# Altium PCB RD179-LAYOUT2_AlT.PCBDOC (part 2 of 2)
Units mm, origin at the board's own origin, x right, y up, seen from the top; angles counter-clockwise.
Board outline 130 x 85 mm, 2 copper layers (TOP, BOTTOM), stack 0 mm thick; 157 components, 104 nets, 823 pads, 0 vias.
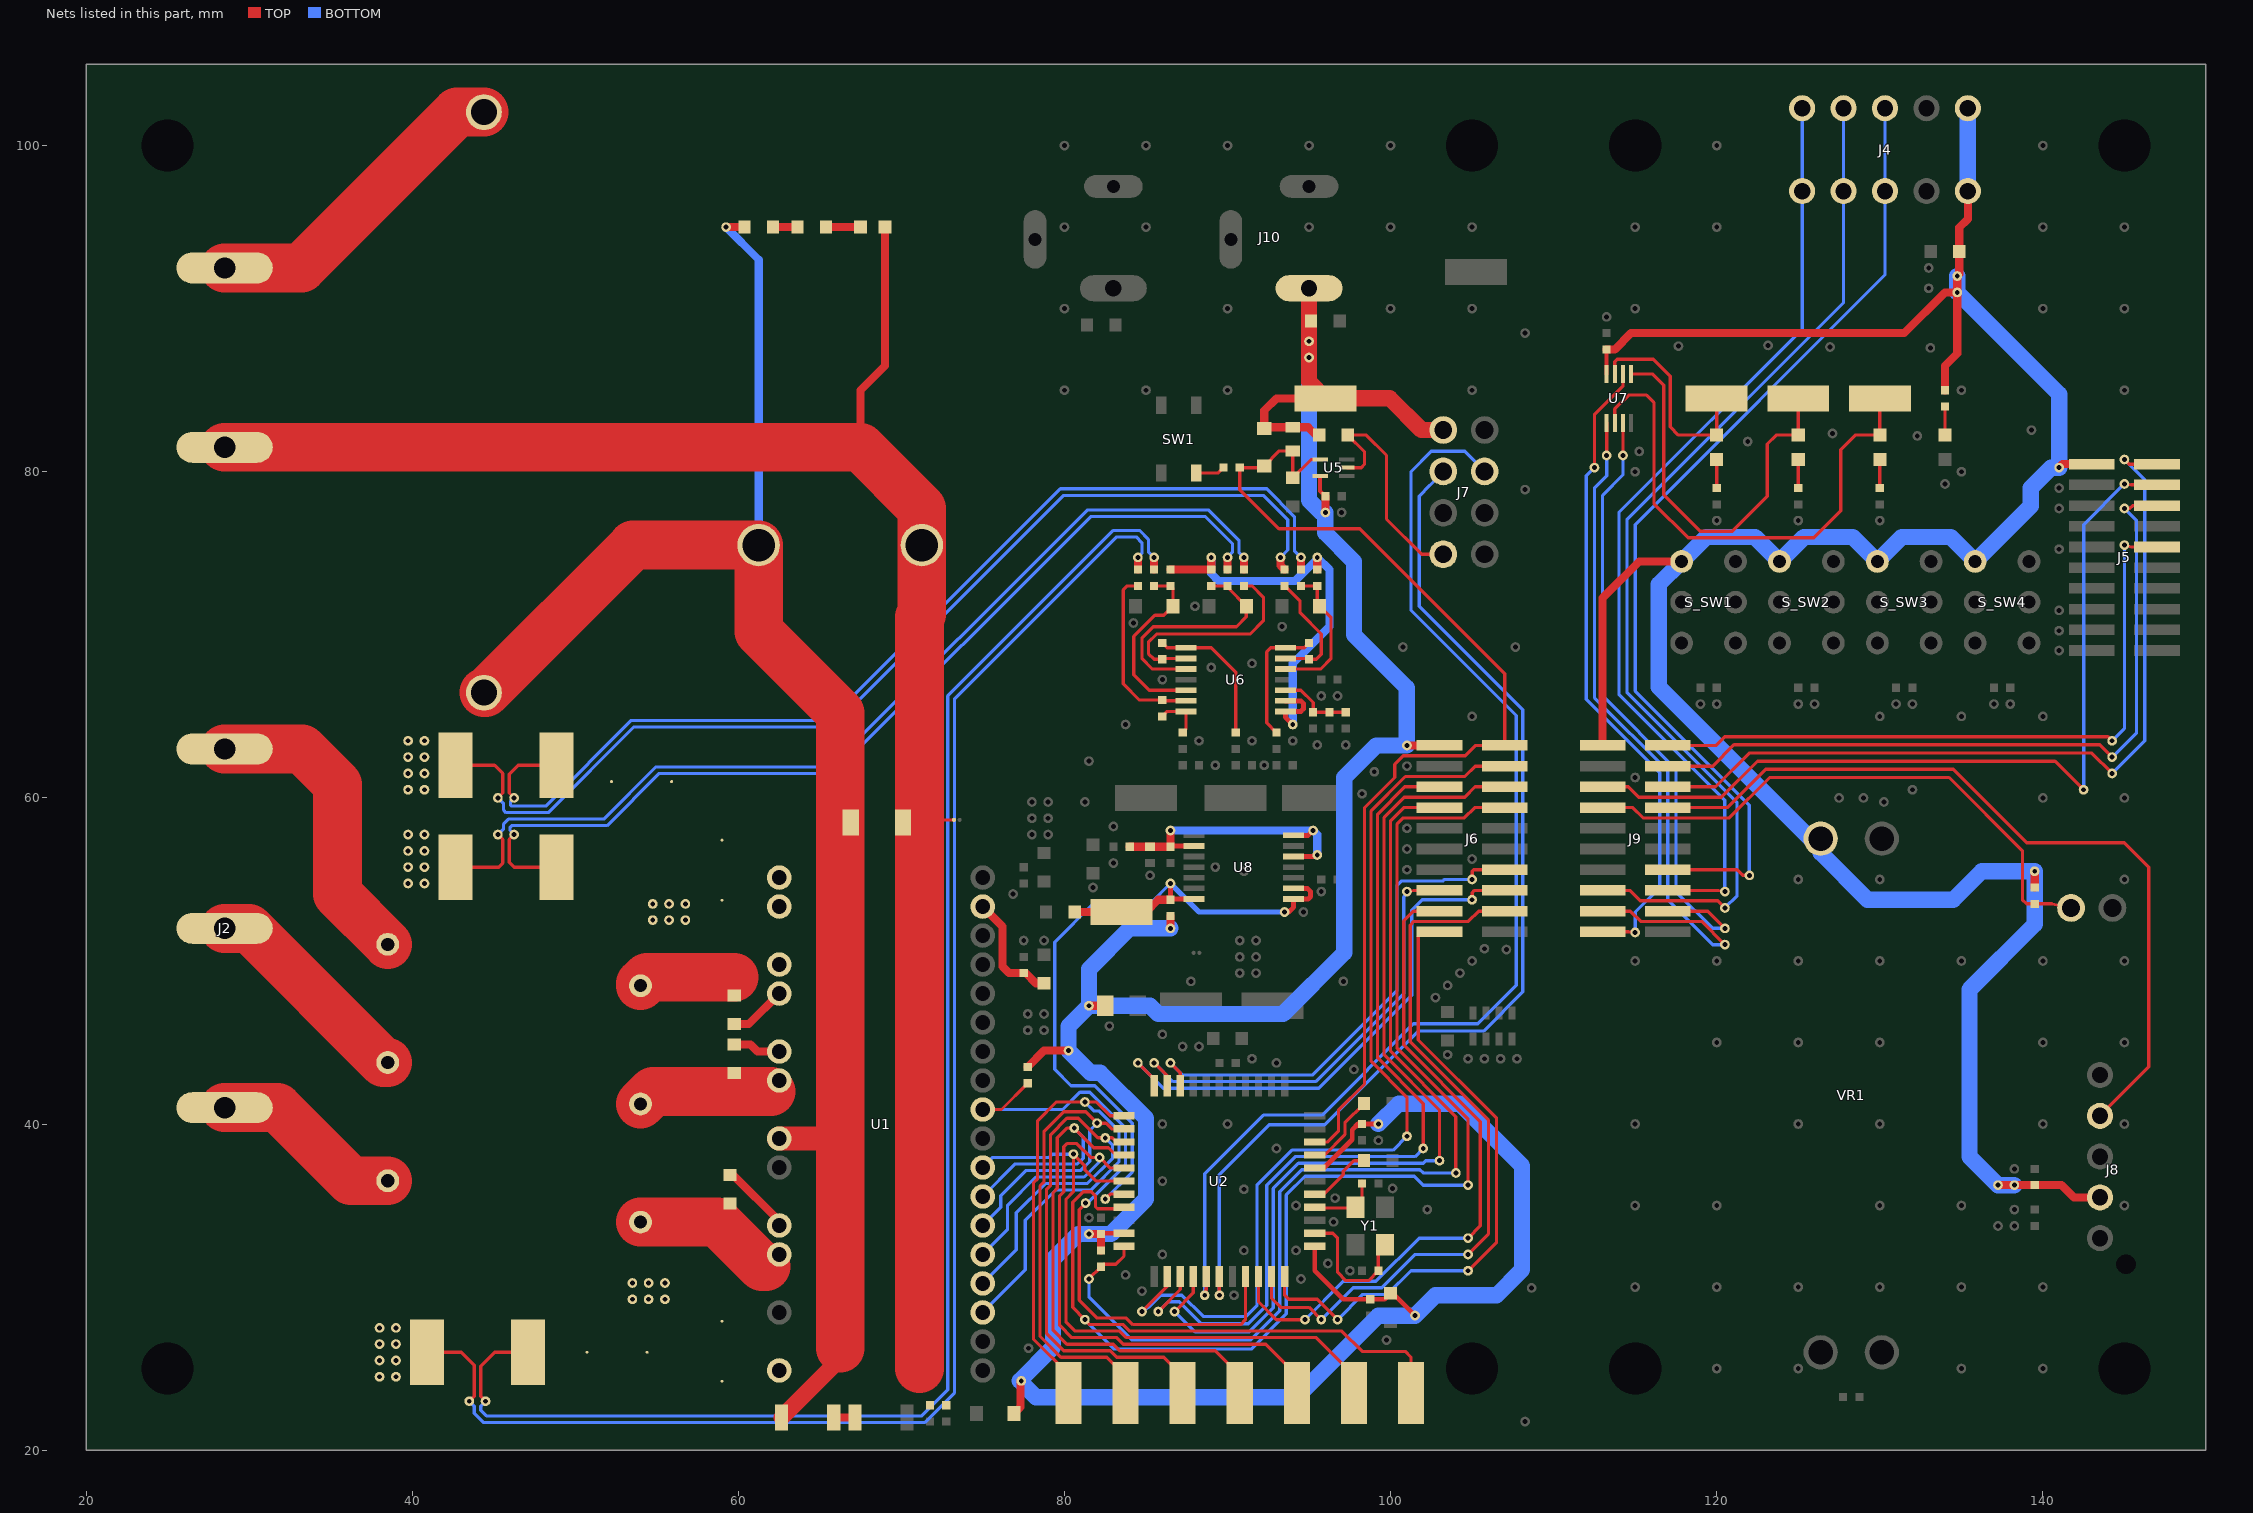
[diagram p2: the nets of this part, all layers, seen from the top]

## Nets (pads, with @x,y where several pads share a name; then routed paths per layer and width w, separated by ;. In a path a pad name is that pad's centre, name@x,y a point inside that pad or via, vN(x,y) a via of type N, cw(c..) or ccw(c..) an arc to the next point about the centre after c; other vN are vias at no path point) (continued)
LED1: J6.17 pad.@94.75,28 pad.@104.75,33 U2.20 | length 41.1
  TOP w0.2: U2.20@91.9,30.65 91.9,29.1 93,28 pad.@94.75,28 ; J6.17@103,53.055 101.4,53.055 100.8,52.455 100.8,44.85 105.5,40.15 105.5,33.75 pad.@104.75,33
  BOTTOM w0.2: pad.@94.75,28 97.1,30.35 99.1,30.35 101.75,33 pad.@104.75,33
LED1X: J9.17 pad.@113.25,81 pad.@120.5,51 U7.1 | length 44.4
  TOP w0.2: J9.17@113,53.055 114.695,53.055 115.33,52.42 119.08,52.42 pad.@120.5,51 ; pad.@113.25,81 U7.1@113.25,83
  BOTTOM w0.2: pad.@113.25,81 113.25,79.75 112.5,79 112.5,66.15 117,61.65 117,53.75 119.75,51 pad.@120.5,51
LED2: J6.18 pad.@95.75,28 pad.@104.75,32 U2.21 | length 44.5
  TOP w0.2: U2.21@92.7,30.65 92.7,29.3 93.25,28.75 95,28.75 pad.@95.75,28 ; pad.@104.75,32 106,33.25 106,40.25 101.2,45.05 101.2,52.2 101.42,52.42 104.77,52.42 105.405,53.055 J6.18@107,53.055
  BOTTOM w0.2: pad.@95.75,28 97.7,29.95 99.45,29.95 101.5,32 pad.@104.75,32
LED2X: J9.18 pad.@114.25,81 pad.@120.5,52 U7.3 | length 39
  TOP w0.2: pad.@114.25,81 U7.3@114.25,83 ; J9.18@117,53.055 119.445,53.055 pad.@120.5,52
  BOTTOM w0.2: pad.@114.25,81 114.25,79.8 113,78.55 113,66.25 117.5,61.75 117.5,54.25 119.75,52 pad.@120.5,52
LED3: J6.19 pad.@96.75,28 pad.@104.75,31 U2.22 | length 38.9
  TOP w0.2: U2.22@93.5,30.65 93.5,29.5 93.75,29.25 95.5,29.25 pad.@96.75,28 ; J6.19@103,51.785 101.985,51.785 101.7,51.5 101.7,45.15 106.5,40.35 106.5,32.75 pad.@104.75,31
  BOTTOM w0.2: pad.@96.75,28 98.3,29.55 99.8,29.55 101.25,31 pad.@104.75,31
LED3X: J9.19 pad.@112.5,80.25 pad.@115,51.75 U7.6 | length 39.7
  TOP w0.2: pad.@112.5,80.25 112.5,83.5 114.25,85.25 U7.6@114.25,86 ; J9.19@113,51.785 114.581,51.785 pad.@115,51.75
  BOTTOM w0.2: pad.@112.5,80.25 112,79.75 112,66.05 116.5,61.55 116.5,54.5 115,53 pad.@115,51.75
N16845104: pad.@89,74.75 pad.@94,64.5 pad.@95.5,74.75 R34.2 R42.2 R49.2 U6.1 U6.2 | length 27.5
  TOP w0.3: U6.2@93.55,65.95 94.5,65.95 94.65,65.8 94.65,65.45 94.5,65.3 U6.1@93.55,65.3 93.55,64.95 pad.@94,64.5
  TOP w0.5: R49.2@86.5,74 R42.2@89,74 pad.@89,74.75 ; R34.2@95.5,74 pad.@95.5,74.75
  BOTTOM w0.5: pad.@89,74.75 89,73.75 89.45,73.3 94.15,73.3 95.5,74.65 pad.@95.5,74.75 96.25,74 96.25,70.5 94,68.25 pad.@94,64.5
N16845135: D6.3 R47.1 R49.1 U6.12 | length 11.4
  TOP w0.2: R47.1@85.5,73 R49.1@86.5,73 86.65,72.85 D6.3@86.65,71.75 86.1,71.2 85.55,71.2 84.25,69.9 84.25,67.55 85.2,66.6 U6.12@87.45,66.6
N16845212: C12.1 U1.22 | length 3.5
  TOP w0.5: C12.1@59.75,46.125 60.639,46.125 U1.22@62.515,48.001
N16845252: SJP1.1 SJP3.2 U1.30
N16845280: pad.@44.5,23 pad.@85.5,74.75 R10.2 R47.2 SJP3.1 | length 96.9
  TOP w0.2: pad.@44.5,23 44.2,23.3 44.2,25.15 45.05,26 R10.2@47.1,26
  TOP w0.5: R47.2@85.5,74 pad.@85.5,74.75
  BOTTOM w0.2: pad.@44.5,23 44.2,22.7 44.2,22.45 44.55,22.1 71.25,22.1 72.85,23.7 72.85,66.25 83,76.4 84.6,76.4 85.15,75.85 85.15,75.1 pad.@85.5,74.75
N16845354: J2.1 L4.1 | length 18.9
  TOP w3: J2.1@28.5,63 33.25,63 35.42,60.83 35.42,54.1 L4.1@38.5,51.02
N16845382: C20.1 U2.27 | length 4
  TOP w0.2: U2.27@95.35,35.7 95.9,35.7 97.1,36.9 97.1,37.1 97.75,37.75 C20.1@98.375,37.75
N16845404: pad.@46.25,57.75 pad.@53.5,29.25 pad.@53.5,30.25 pad.@54.5,29.25 pad.@54.5,30.25 pad.@54.75,52.5 pad.@54.75,53.5 pad.@55.5,29.25 pad.@55.5,30.25 pad.@55.75,52.5 pad.@55.75,53.5 pad.@56.75,52.5 pad.@56.75,53.5 pad.@90,74.75 R11.2 R41.2 SJP1.2 SJP2.1 U1.20 | length 60
  TOP w0.2: pad.@46.25,57.75 45.95,57.45 45.95,56.05 46.25,55.75 R11.2@48.85,55.75
  TOP w0.5: R41.2@90,74 pad.@90,74.75
  BOTTOM w0.2: pad.@46.25,57.75 46,58 46,58.2 46.1,58.3 51.95,58.3 55.15,61.5 65.85,61.5 81.6,77.25 88.65,77.25 90.3,75.6 90.3,75.05 pad.@90,74.75
N16845509: LED1.1 TST1.1 U7.7 | length 13.1
  TOP w0.2: U7.7@113.75,86 113.75,86.75 113.9,86.9 116.1,86.9 117.15,85.85 117.15,82.75 117.65,82.25 LED1.1@120,82.25 TST1.1@120,84.5
N16845541: R37.1 R39.2 U6.8 | length 8.9
  TOP w0.2: R37.1@86,69.5 86.3,69.2 U6.8@87.45,69.2 89,69.2 90.5,67.7 R39.2@90.5,64
N16845574: R27.1 R29.2 U6.7 | length 8
  TOP w0.2: R29.2@93,64 92.4,64.6 92.4,68.95 92.65,69.2 U6.7@93.55,69.2 94.7,69.2 R27.1@95,69.5
N16845576: R37.2 R38.1 U6.9 | length 13.7
  TOP w0.2: U6.9@87.45,68.55 86.05,68.55 R37.2@86,68.5 85.5,68.5 85.15,68.85 85.15,69.55 85.65,70.05 91.4,70.05 92.2,70.85 92.2,72.3 91.5,73 R38.1@91,73
N16845623: SJP2.2 SJP4.2 U1.19
N16845627: C10.2 L3.2 U1.24 | length 8.3
  TOP w3: L3.2@54,41.23 54.77,42 62,42
N16845698: C35.1 pad.@86.5,58 pad.@95.5,56.5 pad.@95.25,58 R33.2 R48.1 U8.5 U8.7 U8.9 | length 18.1
  TOP w0.3: C35.1@86.5,57 86.55,57.05 U8.9@87.95,57.05 ; U8.5@94.05,56.4 95.4,56.4 pad.@95.5,56.5 ; U8.7@94.05,57.7 94.95,57.7 pad.@95.25,58
  TOP w0.5: R33.2@84,57 R48.1@85.25,57 C35.1@86.5,57 pad.@86.5,58
  BOTTOM w0.5: pad.@86.5,58 pad.@95.25,58 95.5,57.75 pad.@95.5,56.5
N16845732: D4.3 R32.1 R34.1 U6.5 | length 8.9
  TOP w0.2: U6.5@93.55,67.9 95.7,67.9 96.35,68.55 96.35,71.05 D4.3@95.65,71.75 95.5,71.9 R34.1@95.5,73 R32.1@94.5,73
N16845798: C12.2 L4.2 U1.21 | length 6
  TOP w3: L4.2@54,48.48 54,48.609 54.391,49 59.75,49
N16846050: C21.1 U2.30 | length 4.8
  TOP w0.2: U2.30@95.35,38.1 95.95,38.1 97.2,39.35 97.2,40.075 C21.1@98.375,41.25
N16846127: F1.1 J1.1 | length 19.9
  TOP w3: J1.1@28.5,92.5 33.2,92.5 42.75,102.05 F1.1@44.4,102.05
N16846135: C10.1 U1.23 | length 2.9
  TOP w0.5: C10.1@59.75,44.875 60.75,44.875 61.18,44.445 U1.23@62.515,44.445
N16846208: R27.2 R28.1 U6.6 | length 7.5
  TOP w0.2: R28.1@93.5,73 94.45,72.05 94.45,71.35 95.75,70.05 95.75,68.8 95.45,68.5 R27.2@95,68.5 94.9,68.5 94.85,68.55 U6.6@93.55,68.55
N16846250: C14.1 C15.1 U1.17 | length 7.2
  TOP w0.5: U1.17@74.985,53.335 76.2,52.12 76.2,49.65 76.6,49.25 C15.1@77.5,49.25 77.625,49.25 78.25,48.625 C14.1@78.75,48.625
N16846295: D5.3 R41.1 R42.1 U6.10 | length 14.5
  TOP w0.2: U6.10@87.45,67.9 85.4,67.9 84.75,68.55 84.75,69.8 85.45,70.5 90.55,70.5 91.15,71.1 D5.3@91.15,71.75 90,72.9 R41.1@90,73 R42.1@89,73
N16846330: C9.1 U1.27 | length 4.4
  TOP w0.5: C9.1@59.5,36.875 59.675,36.875 62.515,34.035 U1.27@62.515,33.777
N16846464: R44.1 R46.2 U6.14 | length 3
  TOP w0.2: R44.1@86,65 86.3,65.3 U6.14@87.45,65.3 87.45,64.2 R46.2@87.25,64
N16846585: C24.1 U2.26 Y1.3 | length 4.3
  TOP w0.2: U2.26@95.35,34.9 95.4,34.85 97.8,34.85 Y1.3@97.85,34.9 98.25,35.3 C24.1@98.25,36.5
N16846619: C16.1 U2.24 Y1.1 | length 8.4
  TOP w0.2: U2.24@95.35,33.3 96.45,33.3 96.75,33 96.75,30.9 97.25,30.4 98.65,30.4 C16.1@99.25,31 99.25,32.25 99.6,32.6 Y1.1@99.65,32.6
N16846795: C9.2 L2.2 U1.28 | length 8.8
  TOP w3: L2.2@54,33.98 58.72,33.98 61.45,31.25 61.7,31.25
N16847047: J2.3 L2.1 | length 11.9
  TOP w3: J2.3@28.5,41 31.75,41 36.23,36.52 L2.1@38.5,36.52
N16847149: LED3.1 TST3.1 U7.2 | length 31.8
  TOP w0.2: U7.2@113.75,83 113.75,83.85 114.6,84.7 115.7,84.7 116.15,84.25 116.15,78.05 118.25,75.95 125.95,75.95 127.6,77.6 127.6,81.35 128.5,82.25 LED3.1@130,82.25 TST3.1@130,84.5
N16847210: R44.2 R45.1 U6.13 | length 11
  TOP w0.2: R45.1@84.5,73 83.85,73 83.6,72.75 83.6,67 84.6,66 R44.2@86,66 86.05,65.95 U6.13@87.45,65.95
N16847386: LED2.1 TST2.1 U7.5 | length 24.7
  TOP w0.2: U7.5@114.75,86 116.05,86 116.75,85.3 116.75,78.6 119,76.35 120.95,76.35 123.1,78.5 123.1,81.7 123.65,82.25 LED2.1@125,82.25 TST2.1@125,84.5
N16847824: pad.@46.25,60 pad.@94.5,74.75 R12.2 R32.2 SJP4.1 | length 65.5
  TOP w0.2: pad.@46.25,60 45.95,60.3 45.95,61.45 46.5,62 R12.2@48.85,62
  TOP w0.5: R32.2@94.5,74 pad.@94.5,74.75
  BOTTOM w0.2: pad.@46.25,60 46.025,59.775 46.025,59.575 46.1,59.5 48.184,59.5 53.434,64.75 65.55,64.75 79.75,78.95 92.4,78.95 94.1,77.25 94.1,75.15 pad.@94.5,74.75
N16854424: J2.2 L3.1 | length 13.4
  TOP w3: J2.2@28.5,52 30,52 38.23,43.77 L3.1@38.5,43.77
N16936899: LEDP1.1 R3.2 | length 2.1
  TOP w0.5: R3.2@65.375,95 LEDP1.1@67.5,95
N16997175: C13.2 R6.2 R7.1 U6.3 | length 4.6
  TOP w0.2: U6.3@93.55,66.6 94.5,66.6 95.25,65.85 C13.2@95.25,65.25 R7.1@96.25,65.25 R6.2@97.25,65.25
N168453641: R1.2 R3.1 | length 1.5
  TOP w0.5: R1.2@62.125,95 R3.1@63.625,95
N168456521: LED1.2 R25.1 | length 1.8
  TOP w0.2: R25.1@120,79 LED1.2@120,80.75
N168457540: LED3.2 R36.1 | length 1.8
  TOP w0.2: R36.1@130,79 LED3.2@130,80.75
N168464781: R16.2 SW1.2 | length 1.8
  TOP w0.2: SW1.2@88.075,79.925 89.425,79.925 R16.2@89.75,80.25
N168466560: R2.2 R4.1 | length 1.3
  TOP w0.5: R2.2@65.85,22 R4.1@67.15,22
N168470940: LEDP2.1 R15.1 | length 1.7
  TOP w0.2: LEDP2.1@134,82.25 R15.1@134,84
N168482340: LED2.2 R30.1 | length 1.8
  TOP w0.2: R30.1@125,79 LED2.2@125,80.75
NBOOT: J6.7 pad.@81.5,30.5 pad.@104,37 R17.2 U2.11 | length 63.3
  TOP w0.2: pad.@81.5,30.5 R17.2@82.25,31.25 82.4,31.4 83.15,31.4 83.65,31.9 U2.11@83.65,32.5 ; J6.7@103,59.405 100.805,59.405 100,58.6 100,44.45 104,40.45 pad.@104,37
  BOTTOM w0.2: pad.@81.5,30.5 81.5,29.4 84.15,26.75 91.397,26.75 93.2,28.553 93.2,35.85 94.55,37.2 101.8,37.2 102,37 pad.@104,37
NBOOTX: J9.7 JP1.1 R22.2 | length 35
  TOP w0.2: J9.7@113,59.405 114.845,59.405 115.48,58.77 120.77,58.77 123.25,61.25 134.25,61.25 138.75,56.75 138.75,53.75 139,53.5 R22.2@139.5,53.5 140.567,53.5 JP1.1@141.73,53.25
NEMG: pad.@82.5,35.4 pad.@86.5,54.75 pad.@93.5,53 R35.2 R43.2 TP11.1 U2.7 U8.1 U8.2 U8.14 | length 49.2
  TOP w0.2: pad.@82.5,35.4 82.8,35.7 U2.7@83.65,35.7
  TOP w0.3: pad.@86.5,54.75 R35.2@86.5,53.75 86.55,53.8 U8.14@87.95,53.8 ; pad.@93.5,53 93.75,53 94.05,53.3 U8.1@94.05,53.8 94.95,53.8 95.1,53.95 95.1,54.25 94.9,54.45 U8.2@94.05,54.45
  TOP w0.5: R43.2@80.625,53 TP11.1@83.5,53 85,53 85.75,53.75 R35.2@86.5,53.75
  BOTTOM w0.2: pad.@82.5,35.4 84.15,37.05 84.15,40.05 81.85,42.35 80.4,42.35 79.4,43.35 79.4,51.15 81.75,53.5 85.25,53.5 pad.@86.5,54.75
  BOTTOM w0.3: pad.@86.5,54.75 88.25,53 pad.@93.5,53
NRESET: C27.1 D2.1 J6.2 R14.1 R16.1 U2.31 U5.4 | length 67
  TOP w0.2: U2.31@95.35,38.9 96.15,38.9 96.8,39.55 96.8,40.85 98.4,42.45 98.4,59.4 100.25,61.25 100.25,62.05 100.78,62.58 104.58,62.58 105.215,63.215 J6.2@107,63.215 107,67.609 98.109,76.5 93.15,76.5 90.75,78.9 R16.1@90.75,80.25 92.15,80.25 D2.1@92.25,80.35 93.175,81.275 R14.1@94,81.275 C27.1@94,79.625 95.125,80.75 U5.4@95.675,80.75
NRESETX: J5.10 J9.2 pad.@144.25,63.5 pad.@145,75.5 | length 41.9
  TOP w0.2: J9.2@117,63.215 119.965,63.215 120.5,63.75 144,63.75 pad.@144.25,63.5 ; pad.@145,75.5 145.404,75.385 J5.10@147,75.385
  BOTTOM w0.2: pad.@144.25,63.5 145,64.25 pad.@145,75.5
NRESIN: J7.7 R54.2 U5.2 | length 14.5
  TOP w0.2: U5.2@97.325,80.25 98.2,80.25 98.4,80.45 98.4,81.225 R54.2@97.375,82.25 98.5,82.25 99.75,81 99.75,77.1 101.91,74.94 J7.7@103.23,74.94
NSD: pad.@81.3,35.15 R13.1 U1.10 U2.19 | length 38.9
  TOP w0.2: U1.10@74.985,40.889 76.139,40.889 R13.1@77.75,42.5 ; pad.@81.3,35.15 80.9,34.75 80.9,29.2 82,28.1 83.8,28.1 84.2,27.7 90.8,27.7 91.1,28 U2.19@91.1,30.65
  BOTTOM w0.2: U1.10@74.985,40.889 79.889,40.889 80.95,41.95 81.55,41.95 83.75,39.75 83.75,37.5 81.4,35.15 pad.@81.3,35.15
NSYNC_SPI: J6.14 pad.@86.5,43.75 pad.@105,55 U2.42 | length 31.7
  TOP w0.2: pad.@86.5,43.75 87.1,43.15 U2.42@87.1,42.35 ; pad.@105,55 105,55.5 105.095,55.595 J6.14@107,55.595
  BOTTOM w0.2: pad.@86.5,43.75 87.25,43 95.2,43 100.4,48.2 100.4,54.65 100.65,54.9 103.2,54.9 103.3,55 pad.@105,55
NSYNC_SPIX: J4.3 J4.3-2 J9.14 pad.@122,55.25 | length 61.4
  TOP w0.2: J9.14@117,55.595 121.25,55.595 121.595,55.25 pad.@122,55.25
  BOTTOM w0.2: pad.@122,55.25 122,59.55 115,66.55 115,76.75 130.32,92.07 J4.3-2@130.32,97.21 J4.3@130.32,102.29
PGND: C8.2 C36.2 C37.2 J1.2 LEDP1.2 pad.@38,24.5 pad.@38,25.5 pad.@38,26.5 pad.@38,27.5 pad.@39,24.5 pad.@39,25.5 pad.@39,26.5 pad.@39,27.5 pad.@39.75,54.75 pad.@39.75,55.75 pad.@39.75,56.75 pad.@39.75,57.75 pad.@39.75,60.5 pad.@39.75,61.5 pad.@39.75,62.5 pad.@39.75,63.5 pad.@40.75,54.75 pad.@40.75,55.75 pad.@40.75,56.75 pad.@40.75,57.75 pad.@40.75,60.5 pad.@40.75,61.5 pad.@40.75,62.5 pad.@40.75,63.5 pad.@43.5,23 pad.@45.25,57.75 pad.@45.25,60 pad.@84.5,74.75 pad.@91,74.75 pad.@93.25,74.75 R5.2 R9.2 R10.1 R11.1 R12.1 R28.2 R38.2 R45.2 | length 338.6
  TOP w0.2: R10.1@40.9,26 43,26 43.8,25.2 43.8,23.3 pad.@43.5,23 ; R11.1@42.65,55.75 45.3,55.75 45.55,56 45.55,57.45 pad.@45.25,57.75 ; R12.1@42.65,62 45.05,62 45.55,61.5 45.55,60.3 pad.@45.25,60 ; C8.2@70.1,58.5 70.25,58.65 71.1,58.65 R9.2@73.225,58.65
  TOP w0.5: 67.5,81.5 67.5,85 69,86.5 LEDP1.2@69,95 ; R45.2@84.5,74 pad.@84.5,74.75 ; R38.2@91,74 pad.@91,74.75 ; pad.@93.25,74.75 93.25,74.25 R28.2@93.5,74
  TOP w3: J1.2@28.5,81.5 67.5,81.5 71.25,77.75 C36.2@71.25,75.5 71.25,71.25 71.1,71.1 71.1,58.65 71.1,25
  BOTTOM w0.2: pad.@43.5,23 43.8,22.7 43.8,22.25 44.35,21.7 71.45,21.7 73.25,23.5 73.25,66.05 83.2,76 84.4,76 84.75,75.65 84.75,75 pad.@84.5,74.75 ; pad.@45.25,57.75 45.6,58.1 45.6,58.4 45.9,58.7 51.75,58.7 54.95,61.9 65.65,61.9 81.4,77.65 88.85,77.65 90.7,75.8 90.7,75.05 pad.@91,74.75 ; pad.@45.25,60 45.6,59.65 45.6,59.25 45.75,59.1 48.35,59.1 53.6,64.35 65.75,64.35 79.95,78.55 92.2,78.55 93.7,77.05 93.7,75.2 pad.@93.25,74.75
RELAY: J6.8 pad.@81.25,28 pad.@104.75,36.25 TP1.1 U2.8 | length 99.1
  TOP w0.2: U2.8@83.65,34.9 83.55,34.8 82.041,34.8 81.9,34.941 81.9,35.6 81.65,35.85 81.15,35.85 80.5,35.2 80.5,28.75 pad.@81.25,28 81.55,27.7 83.6,27.7 84,27.3 97,27.3 98.25,26.05 100.9,26.05 101.25,25.7 TP1.1@101.25,23.5 ; pad.@104.75,36.25 104.75,40.3 100.4,44.65 100.4,58.4 100.77,58.77 104.52,58.77 105.155,59.405 J6.8@107,59.405
  BOTTOM w0.2: pad.@81.25,28 83.05,26.2 91.45,26.2 93.6,28.35 93.6,35.65 94.75,36.8 101.45,36.8 102,36.25 pad.@104.75,36.25
RELAYX: J8.4 J9.8 | length 49.4
  TOP w0.2: J9.8@117,59.405 120.655,59.405 123,61.75 134.5,61.75 139,57.25 145,57.25 146.5,55.75 146.5,43.5 J8.4@143.5,40.5
RXD_UA_MCU: J7.3 pad.@89.5,29.5 U2.17 | length 66.9
  TOP w0.2: pad.@89.5,29.5 U2.17@89.5,30.65
  BOTTOM w0.2: pad.@89.5,29.5 89.5,36.9 92.55,39.95 95.95,39.95 101.7,45.7 105.7,45.7 108.1,48.1 108.1,65.4 101.75,71.75 101.75,78.5 102.409,79.159 J7.3@103.23,80.02
SCLK_SPI: J6.16 pad.@84.5,43.75 pad.@105,53.75 U2.44 | length 33.3
  TOP w0.2: pad.@84.5,43.75 85.5,42.75 U2.44@85.5,42.35 ; pad.@105,53.75 105,54.184 105.141,54.325 J6.16@107,54.325
  BOTTOM w0.2: pad.@84.5,43.75 86.05,42.2 95.6,42.2 101.3,47.9 101.3,53.109 101.941,53.75 pad.@105,53.75
SCLK_SPIX: J4.5 J4.5-2 J9.16 pad.@120.5,54.25 | length 58.9
  TOP w0.2: J9.16@117,54.325 120.087,54.325 pad.@120.5,54.25
  BOTTOM w0.2: pad.@120.5,54.25 120.5,59.85 114,66.35 114,77.5 125.24,88.74 J4.5-2@125.24,97.21 J4.5@125.24,102.29
SDO_SPI: J6.15 pad.@85.5,43.75 pad.@101,54.25 U2.43 | length 28.1
  TOP w0.2: pad.@85.5,43.75 86.3,42.95 U2.43@86.3,42.35 ; pad.@101,54.25 101.413,54.325 J6.15@103,54.325
  BOTTOM w0.2: pad.@85.5,43.75 86.65,42.6 95.4,42.6 100.8,48 100.8,53.9 pad.@101,54.25
SDO_SPIX: J4.4 J4.4-2 J9.15 pad.@120.5,53.25 | length 65.6
  TOP w0.2: J9.15@113,54.325 114.675,54.325 115.31,53.69 120.06,53.69 pad.@120.5,53.25
  BOTTOM w0.2: pad.@120.5,53.25 121.25,54 121.25,59.7 114.5,66.45 114.5,77.1 127.78,90.38 J4.4-2@127.78,97.21 J4.4@127.78,102.29
SWCLK: J6.5 pad.@85.75,28.5 pad.@102,38.5 U2.14 | length 54.7
  TOP w0.2: pad.@85.75,28.5 87.1,29.85 U2.14@87.1,30.65 ; pad.@102,38.5 102,41.25 99.2,44.05 99.2,59 100.875,60.675 J6.5@103,60.675
  BOTTOM w0.2: pad.@85.75,28.5 86.35,29.1 87.034,29.1 88.384,27.75 91.266,27.75 92.4,28.884 92.4,36.25 94.15,38 101.5,38 pad.@102,38.5
SWCLKX: J5.4 J9.5 pad.@142.5,60.5 pad.@145,79.25 | length 53.2
  TOP w0.2: J9.5@113,60.675 114.575,60.675 115.21,60.04 120.29,60.04 122.5,62.25 140.75,62.25 pad.@142.5,60.5 ; pad.@145,79.25 145.416,79.195 J5.4@147,79.195
  BOTTOM w0.2: pad.@142.5,60.5 142.5,76.75 pad.@145,79.25
SWDIO: J6.6 pad.@86.75,28.5 pad.@103,37.75 U2.15 | length 58.7
  TOP w0.2: pad.@86.75,28.5 87.9,29.65 U2.15@87.9,30.65 ; pad.@103,37.75 103,40.85 99.6,44.25 99.6,58.8 100.84,60.04 104.54,60.04 105.175,60.675 J6.6@107,60.675
  BOTTOM w0.2: pad.@86.75,28.5 88,27.25 91.331,27.25 92.8,28.719 92.8,36.05 94.35,37.6 102,37.6 102.15,37.75 pad.@103,37.75
SWDIOX: J5.2 J9.6 pad.@144.25,61.5 pad.@145,80.75 | length 51.3
  TOP w0.2: J9.6@117,60.675 119.925,60.675 122,62.75 143,62.75 pad.@144.25,61.5 ; pad.@145,80.75 145.285,80.465 J5.2@147,80.465
  BOTTOM w0.2: pad.@144.25,61.5 146.25,63.5 146.25,79.5 pad.@145,80.75
SWV: J6.4 pad.@84.75,28.5 pad.@101,39.25 U2.13 | length 59.1
  TOP w0.2: pad.@84.75,28.5 86.3,30.05 U2.13@86.3,30.65 ; pad.@101,39.25 101,41.65 98.8,43.85 98.8,59.2 100.91,61.31 104.56,61.31 105.195,61.945 J6.4@107,61.945
  BOTTOM w0.2: pad.@84.75,28.5 85.2,28.8 85.9,29.5 87.2,29.5 88.5,28.2 91.15,28.2 91.8,28.85 91.8,36.25 93.95,38.4 100.15,38.4 pad.@101,39.25
SWVX: J5.6 J9.4 pad.@144.25,62.5 pad.@145,77.75 | length 46.4
  TOP w0.2: J9.4@117,61.945 119.75,61.945 121.055,63.25 143.5,63.25 pad.@144.25,62.5 ; pad.@145,77.75 145.325,77.75 145.5,77.925 J5.6@147,77.925
  BOTTOM w0.2: pad.@144.25,62.5 145.75,64 145.75,77 pad.@145,77.75
TXD_UA_MCU: J7.4 pad.@88.6,29.5 U2.16 | length 72.2
  TOP w0.2: pad.@88.6,29.5 88.7,29.9 U2.16@88.7,30.65
  BOTTOM w0.2: pad.@88.6,29.5 88.6,36.95 92.2,40.55 95.8,40.55 101.4,46.15 105.35,46.15 107.7,48.5 107.7,65.05 101.25,71.5 101.25,80 102.5,81.25 104.54,81.25 J7.4@105.77,80.02
UH_1: pad.@81.25,41.35 TP5.1 U1.3 U2.1 | length 42.5
  TOP w0.2: TP5.1@80.25,23.5 80.25,24.65 78.1,26.8 78.1,36.4 78.35,36.65 78.35,40.2 79.5,41.35 pad.@81.25,41.35 81.95,41.35 82.8,40.5 U2.1@83.65,40.5
  BOTTOM w0.2: U1.3@74.985,28.443 77.6,31.058 77.6,34.1 79.45,35.95 81.6,35.95 83.35,37.7 83.35,39.55 82.1,40.8 81.8,40.8 pad.@81.25,41.35
UL_1: pad.@82,40.05 TP14.1 U1.6 U2.2 | length 37
  TOP w0.2: U2.2@83.65,39.7 82.9,39.7 82.55,40.05 pad.@82,40.05 81.3,40.75 79.95,40.75 78.75,39.55 78.75,36.45 78.5,36.2 78.5,26.984 79.784,25.7 82.6,25.7 83.75,24.55 TP14.1@83.75,23.5
  BOTTOM w0.2: U1.6@74.985,33.777 76.1,34.892 76.1,35.6 77.65,37.15 81,37.15 81.55,37.7 81.55,39.6 pad.@82,40.05
VDD: C3.1 C4.1 C5.1 C18.1 C22.1 C26.1 D1.3 D2.3 J6.1 J7.1 J10.1 L1.2 pad.@77.35,24.25 pad.@80.25,44.5 pad.@81.5,33.25 pad.@81.5,47.25 pad.@86.5,52 pad.@95,87 pad.@95,88 pad.@96,77.5 pad.@99.25,40 pad.@101,63.215 pad.@101.5,28.25 R13.2 R14.2 R17.1 R35.1 R54.1 TP7.1 U2.10 U2.23 U2.29 U5.5 | length 203.6
  TOP w0.25: U5.5@95.675,79.75 95.675,78.825 C26.1@96,78.5
  TOP w0.3: C3.1@82.25,33.25 82.3,33.3 U2.10@83.65,33.3 ; U2.23@95.35,32.5 95.35,31 97.1,29.25 C4.1@98.75,29.25 99.625,29.25 C5.1@100,29.625 100.125,29.625 pad.@101.5,28.25 ; U2.29@95.35,37.3 95.9,37.3 97.65,39.05 97.65,39.65 98,40 C22.1@98.25,40 pad.@99.25,40
  TOP w0.5: D1.3@76.9,22.25 77.3,22.65 77.3,24.25 pad.@77.35,24.25 ; R13.2@77.75,43.5 78.75,44.5 pad.@80.25,44.5 ; pad.@81.5,33.25 C3.1@82.25,33.25 R17.1@82.25,32.25 ; pad.@81.5,47.25 L1.2@82.5,47.25 ; pad.@86.5,52 R35.1@86.5,52.75 ; R54.1@95.625,82.25 95.425,82.25 94.95,82.725 R14.2@94,82.725 92.325,82.725 D2.3@92.25,82.65 92.25,83.75 93,84.5 TP7.1@96,84.5 ; pad.@96,77.5 C26.1@96,78.5 ; pad.@101,63.215 J6.1@103,63.215
  TOP w1: J10.1@95,91.25 95,88.85 pad.@95,88 pad.@95,87 95,85.5 TP7.1@96,84.5 99.95,84.5 101.89,82.56 J7.1@103.23,82.56
  BOTTOM w1: pad.@86.5,52 84,52 81.5,49.5 pad.@81.5,47.25 ; pad.@95,88 95,78.25 95.75,77.5 pad.@96,77.5 96,76.25 97.75,74.5 97.75,70 101,66.75 pad.@101,63.215 99.115,63.215 97.15,61.25 97.15,50.5 93.4,46.75 85.75,46.75 85.25,47.25 pad.@81.5,47.25 ; pad.@99.25,40 100.5,41.25 104.25,41.25 108.06,37.44 108.06,31.06 106.5,29.5 102.75,29.5 pad.@101.5,28.25 99.25,28.25 94.25,23.25 78.25,23.25 pad.@77.25,24.25 ; pad.@77.25,24.25 pad.@77.35,24.25 pad.@77.25,24.25 ; pad.@77.25,24.25 79.3,26.3 79.3,31.7 80.85,33.25 pad.@81.5,33.25 82.85,33.25 85,35.4 85,40.35 82.2,43.15 81.6,43.15 pad.@80.25,44.5 80.25,46 pad.@81.5,47.25
VDDX: C25.1 C29.1 C39.1 J4.1 J4.1-2 J5.1 J8.2 J9.1 pad.@134.75,91 pad.@134.75,92 pad.@137.25,36.25 pad.@138.25,36.25 pad.@139.5,55.5 pad.@141,80.25 R15.2 R22.1 S_SW1.1 S_SW2.1 S_SW3.1 S_SW4.1 U7.8 VR1.3 | length 171.6
  TOP w0.25: U7.8@113.25,86 C29.1@113.25,87.5
  TOP w0.5: J9.1@113,63.215 113,72.25 115.25,74.5 S_SW1.1@117.85,74.5 ; C29.1@113.25,87.5 113.75,87.5 114.75,88.5 131.5,88.5 134,91 pad.@134.75,91 ; R15.2@134,85 134,86.5 134.75,87.25 pad.@134.75,91 ; J4.1-2@135.4,97.21 135.4,95.5 134.875,94.975 C25.1@134.875,93.5 134.875,92.125 pad.@134.75,92 pad.@134.75,91 ; pad.@137.25,36.25 pad.@138.25,36.25 C39.1@139.5,36.25 141.15,36.25 141.9,35.5 J8.2@143.5,35.5 ; R22.1@139.5,54.5 pad.@139.5,55.5 ; pad.@141,80.25 141.215,80.465 J5.1@143,80.465
  BOTTOM w1: pad.@134.75,92 pad.@134.75,91 141,84.75 pad.@141,80.25 140.5,80.25 139.25,79 139.25,77.9 S_SW4.1@135.85,74.5 134.35,76 131.35,76 S_SW3.1@129.85,74.5 128.35,76 125.35,76 S_SW2.1@123.85,74.5 122.35,76 119.35,76 S_SW1.1@117.85,74.5 116.45,73.1 116.45,66.8 125.75,57.5 VR1.3@126.375,57.5 126.375,56.625 129.25,53.75 134.5,53.75 136.25,55.5 pad.@139.5,55.5 139.5,52.25 135.5,48.25 135.5,38 pad.@137.25,36.25 pad.@138.25,36.25 ; J4.1-2@135.4,97.21 J4.1@135.4,102.29
VH_1: pad.@82.5,39.15 TP4.1 U1.4 U2.3 | length 42.2
  TOP w0.2: U2.3@83.65,38.9 83.17,38.9 82.92,39.15 pad.@82.5,39.15 82.05,39.15 80.85,40.35 80.15,40.35 79.15,39.35 79.15,36.25 78.9,36 78.9,27.15 79.95,26.1 82.8,26.1 83.2,25.7 86.1,25.7 87.25,24.55 TP4.1@87.25,23.5
  BOTTOM w0.2: U1.4@74.985,30.221 77.05,32.286 77.05,34.55 78.85,36.35 81.4,36.35 82.95,37.9 82.95,38.7 pad.@82.5,39.15
VL_1: pad.@80.6,39.75 TP15.1 U1.7 U2.4 | length 39.8
  TOP w0.2: U2.4@83.65,38.1 83.15,38.1 82.7,38.55 81.8,38.55 pad.@80.6,39.75 80.15,39.75 79.55,39.15 79.55,36.05 79.3,35.8 79.3,27.35 80.15,26.5 83,26.5 83.4,26.1 89.25,26.1 90.75,24.6 TP15.1@90.75,23.5
  BOTTOM w0.2: U1.7@74.985,35.555 76.98,37.55 80.8,37.55 81.15,37.9 81.15,39.2 pad.@80.6,39.75
VP+: C8.1 C36.1 F1.2 pad.@59.25,95 R1.1 R2.1 U1.25 | length 102.7
  TOP w0.5: pad.@59.25,95 R1.1@60.375,95
  TOP w1: R2.1@62.65,22 65.9,25.25 65.9,26.25
  TOP w1.5: U1.25@62.515,39.111 66.25,39.111
  TOP w3: F1.2@44.4,66.45 44.5,66.45 53.55,75.5 C36.1@61.25,75.5 61.25,70.2 66.25,65.2 66.25,58.5 66.25,39.111 66.25,26.25
  BOTTOM w0.5: pad.@59.25,95 61.25,93 C36.1@61.25,75.5
WH_1: pad.@82.15,37.95 TP3.1 U1.5 U2.5 | length 43
  TOP w0.2: U2.5@83.65,37.3 82.8,37.3 pad.@82.15,37.95 81.6,37.95 80.75,38.8 80.15,38.8 79.95,38.6 79.95,35.85 79.7,35.6 79.7,27.65 80.45,26.9 83.2,26.9 83.6,26.5 92.35,26.5 94.25,24.6 TP3.1@94.25,23.5
  BOTTOM w0.2: U1.5@74.985,31.999 76.5,33.514 76.5,35 78.25,36.75 81.2,36.75 82.15,37.7 pad.@82.15,37.95
WL_1: pad.@80.55,38.15 TP16.1 U1.8 U2.6 | length 41.3
  TOP w0.2: U2.6@83.65,36.5 81.95,36.5 81.25,37.2 81.25,37.45 pad.@80.55,38.15 80.55,35.85 80.1,35.4 80.1,27.85 80.65,27.3 83.4,27.3 83.8,26.9 95.45,26.9 97.75,24.6 TP16.1@97.75,23.5
  BOTTOM w0.2: pad.@80.55,38.15 79.25,38.15 79.05,37.95 75.602,37.95 ; 75.602,37.95 U1.8@74.985,37.333 75.602,37.95
pads on no net: J3.3 J5.7 J5.8 J5.11 J5.12 J5.13 J5.14 J5.16 J5.18 J5.20 J8. J10.3 PAP1. PAP2. PAP3. PAP4. PAP5. PAP6. PAP7. PAP8. S_SW1.4 S_SW1.5 S_SW1.6 S_SW2.4 S_SW2.5 S_SW2.6 S_SW3.4 S_SW3.5 S_SW3.6 S_SW4.4 S_SW4.5 S_SW4.6 SW1.1 SW1.3 U1.2 U1.9 U1.11 U1.13 U1.15 U1.26 U1.29 U5.1 U8.13 VR1.4

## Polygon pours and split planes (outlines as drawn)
no net on Top Overlay "TOPOVERLAY42" (solid, pour order 0): 67.946,99 67.946,101.438 69.468,101.438 cw(c69.468,100.887) 70.02,100.887 70.02,100.734 cw(c69.566,100.734) 69.594,100.281 69.594,100.279 cw(c69.561,99.777) 70.064,99.777 70.064,99.584 cw(c69.48,99.584) 69.48,99
no net on Top Overlay "TOPOVERLAY43" (solid, pour order 0): 71.963,98.989 71.825,99.463 71.04,99.463 70.905,99 70.197,99 70.947,101.438 71.918,101.438 72.672,98.989
no net on Top Overlay "TOPOVERLAY44" (solid, pour order 0): 59.489,98.956 cw(c59.489,99.767) 58.677,99.767 58.677,100.682 cw(c59.489,100.682) 59.489,101.494 60.172,101.494 cw(c60.172,100.682) 60.983,100.682 60.983,99.767 cw(c60.172,99.767) 60.172,98.956
PGND on TOP "TOP1" (solid, pour order 8): 24.575,80 cw(c24.575,80.075) 24.5,80.075 24.5,82.925 cw(c24.575,82.925) 24.575,83 31.675,83 cw(c31.675,82.925) 31.75,82.925 31.75,80.075 cw(c31.675,80.075) 31.675,80
PGND on TOP "TOP2" (solid, pour order 9): 71.331,22.5 cw(c71.331,22.575) 71.278,22.522 70.903,22.897 cw(c70.957,22.95) 70.897,22.904 ccw(c70.7,22.75) 70.854,22.947 cw(c70.9,23.006) 70.847,22.953 69.622,24.178 cw(c69.675,24.231) 69.6,24.231 69.6,25.425 cw(c69.675,25.425) 69.675,25.5 72.525,25.5 cw(c72.525,25.425) 72.6,25.425 72.6,24.15 72.978,23.772 cw(c72.925,23.719) 73,23.719 73,22.575 cw(c72.925,22.575) 72.925,22.5
+15 on TOP "TOP3" (solid, pour order 10): 82.6,90.175 cw(c82.675,90.175) 82.675,90.25 83.425,90.25 cw(c83.425,90.175) 83.5,90.175 83.5,89.675 cw(c83.425,89.675) 83.425,89.6 82.8,89.6 ccw(c82.8,89.35) 82.704,89.581 cw(c82.675,89.65) 82.6,89.65
+15 on TOP "TOP4" (solid, pour order 11): 82.675,88.1 cw(c82.675,88.175) 82.6,88.175 82.6,88.35 cw(c82.675,88.35) 82.704,88.419 ccw(c82.8,88.65) 82.8,88.4 83.425,88.4 cw(c83.425,88.325) 83.5,88.325 83.5,88.175 cw(c83.425,88.175) 83.425,88.1
AGND on TOP "TOP5" (solid, pour order 12): 93.825,61 cw(c93.825,61.075) 93.75,61.075 93.75,61.475 cw(c93.825,61.475) 93.825,61.55 94.2,61.55 ccw(c94.2,61.8) 94.45,61.8 94.45,62.2 ccw(c94.2,62.2) 94.2,62.45 93.8,62.45 ccw(c93.8,62.2) 93.774,62.449 cw(c93.766,62.523) 93.75,62.45 93.525,62.45 cw(c93.525,62.525) 93.45,62.525 93.45,63.925 cw(c93.525,63.925) 93.525,64 94,64 ccw(c94,64.5) 94.433,64.25 ccw(c94,64.5) 94.496,64.434 cw(c94.57,64.425) 94.57,64.5 94.725,64.5 cw(c94.725,64.425) 94.8,64.425 94.8,64.05 ccw(c95.05,64.05) 95.05,63.8 96.725,63.8 cw(c96.725,63.725) 96.8,63.725 96.8,63.485 cw(c96.725,63.485) 96.793,63.454 ccw(c97.25,63.25) 97.402,62.774 97.404,62.774 ccw(c97.25,63.25) 97.707,63.454 cw(c97.775,63.485) 97.7,63.485 97.7,65.45 ccw(c97.45,65.45) 97.45,65.7 96.325,65.7 cw(c96.325,65.775) 96.25,65.775 96.25,66.725 cw(c96.325,66.725) 96.325,66.8 96.95,66.8 ccw(c96.95,67.05) 97.2,67.05 97.2,67.425 cw(c97.275,67.425) 97.275,67.5 97.469,67.5 cw(c97.469,67.425) 97.522,67.478 98.478,66.522 cw(c98.425,66.469) 98.5,66.469 98.5,63.281 cw(c98.425,63.281) 98.478,63.228 97.478,62.228 97.272,62.022 96.272,61.022 cw(c96.219,61.075) 96.219,61
AGND on TOP "TOP6" (solid, pour order 13): 87.325,49.25 cw(c87.325,49.325) 87.25,49.325 87.25,51.925 cw(c87.325,51.925) 87.325,52 89.175,52 cw(c89.175,51.925) 89.25,51.925 89.25,49.325 cw(c89.175,49.325) 89.175,49.25
GND on TOP "TOP7" (solid, pour order 14): 86.5,48.25 cw(c86.5,48.325) 86.425,48.325 86.425,51.425 cw(c86.5,51.425) 86.5,51.5 ccw(c86.5,52) 86.996,51.935 cw(c87.07,51.925) 87.07,52 87.425,52 cw(c87.425,51.925) 87.5,51.925 87.5,49.224 cw(c87.425,49.224) 87.467,49.163 ccw(c87.75,48.75) 87.317,49 ccw(c87.75,48.75) 87.38,48.413 cw(c87.325,48.363) 87.4,48.363 87.4,48.325 cw(c87.325,48.325) 87.325,48.25
GND on TOP "TOP8" (solid, pour order 15): 69.825,57 cw(c69.825,57.075) 69.75,57.075 69.75,61.425 cw(c69.825,61.425) 69.825,61.5 75.175,61.5 cw(c75.175,61.425) 75.25,61.425 75.25,57.075 cw(c75.175,57.075) 75.175,57
+15 on TOP "TOP9" (solid, pour order 16): 82.575,87.25 cw(c82.575,87.325) 82.5,87.325 82.5,89.925 cw(c82.575,89.925) 82.575,90 83.425,90 cw(c83.425,89.925) 83.5,89.925 83.5,87.325 cw(c83.425,87.325) 83.425,87.25
GND on TOP "TOP10" (solid, pour order 17): 77.275,44.95 cw(c77.275,45.025) 77.2,45.025 77.2,46.975 cw(c77.275,46.975) 77.275,47.05 79.25,47.05 ccw(c79.25,47.5) 79.568,47.182 79.918,47.532 ccw(c79.6,47.85) 80.05,47.85 80.05,51.925 cw(c80.125,51.925) 80.125,52 85.93,52 cw(c85.93,51.925) 86.004,51.935 ccw(c86.5,52) 86.5,51.5 cw(c86.5,51.425) 86.575,51.425 86.575,48.325 cw(c86.5,48.325) 86.5,48.25 85.9,48.25 ccw(c85.9,48) 85.678,48.115 cw(c85.612,48.15) 85.612,48.075 82.05,48.075 ccw(c82.05,47.825) 81.8,47.825 81.8,47.779 cw(c81.725,47.779) 81.696,47.71 ccw(c81.5,47.25) 81.696,46.79 cw(c81.725,46.721) 81.8,46.721 81.8,46.675 ccw(c82.05,46.675) 82.05,46.425 85.612,46.425 cw(c85.612,46.35) 85.678,46.385 ccw(c85.9,46.5) 85.9,46.25 86.425,46.25 cw(c86.425,46.175) 86.5,46.175 86.5,45.224 cw(c86.425,45.224) 86.467,45.163 ccw(c86.75,44.75) 86.311,44.989 cw(c86.245,45.025) 86.245,44.95 80.485,44.95 cw(c80.485,45.025) 80.454,44.957 ccw(c80.25,44.5) 80.046,44.957 cw(c80.015,45.025) 80.015,44.95
AGND on TOP "TOP11" (solid, pour order 18): 88.875,48.35 cw(c88.875,48.425) 88.8,48.425 88.8,56.875 cw(c88.875,56.875) 88.875,56.95 89.395,56.95 cw(c89.395,56.875) 89.448,56.928 89.778,56.598 cw(c89.725,56.545) 89.8,56.545 89.8,54.3 ccw(c90.1,54.3) 89.888,54.088 94.478,49.498 cw(c94.425,49.445) 94.5,49.445 94.5,48.425 cw(c94.425,48.425) 94.425,48.35
AGND on TOP "TOP12" (solid, pour order 19): 81.025,54 cw(c81.025,54.075) 80.95,54.075 80.95,62.429 cw(c81.025,62.429) 80.972,62.482 84.168,65.678 cw(c84.221,65.625) 84.221,65.7 85.475,65.7 cw(c85.475,65.625) 85.55,65.625 85.55,64.8 ccw(c85.8,64.8) 85.8,64.55 86.725,64.55 cw(c86.725,64.475) 86.8,64.475 86.8,62.375 cw(c86.725,62.375) 86.725,62.3 85.5,62.3 ccw(c85.5,62) 85.288,62.212 84.788,61.712 ccw(c85,61.5) 84.7,61.5 84.7,61.075 cw(c84.625,61.075) 84.625,61 83.15,61 ccw(c83.15,60.75) 82.9,60.75 82.9,58.798 cw(c82.825,58.798) 82.848,58.726 ccw(c83,58.25) 82.796,58.707 cw(c82.765,58.775) 82.765,58.7 82,58.7 ccw(c82,58.25) 81.682,58.568 81.432,58.318 ccw(c81.75,58) 81.3,58 81.3,57.724 cw(c81.225,57.724) 81.265,57.661 ccw(c81.4,57.45) 81.15,57.45 81.15,55.05 ccw(c81.4,55.05) 81.4,54.8 82.1,54.8 ccw(c82.1,55.05) 82.35,55.05 82.35,56.475 cw(c82.425,56.475) 82.425,56.55 84.675,56.55 cw(c84.675,56.475) 84.75,56.475 84.75,55.8 ccw(c85,55.8) 85,55.55 85.5,55.55 ccw(c85.5,55.8) 85.75,55.8 85.75,56.175 cw(c85.825,56.175) 85.825,56.25 85.975,56.25 cw(c85.975,56.175) 86.05,56.175 86.05,54.985 cw(c85.975,54.985) 86.043,54.954 ccw(c86.5,54.75) 86.004,54.685 cw(c85.93,54.675) 85.983,54.622 85.383,54.022 cw(c85.33,54.075) 85.33,54
AGND on TOP "TOP13" (solid, pour order 20): 92.446,60.981 ccw(c92.35,60.75) 92.35,61 91.275,61 cw(c91.275,61.075) 91.2,61.075 91.2,61.476 cw(c91.275,61.476) 91.281,61.551 ccw(c91.3,61.8) 91.3,61.55 91.7,61.55 ccw(c91.7,61.8) 91.95,61.8 91.95,62.2 ccw(c91.7,62.2) 91.7,62.45 91.025,62.45 cw(c91.025,62.525) 90.95,62.525 90.95,64.2 ccw(c90.7,64.2) 90.835,64.411 cw(c90.875,64.474) 90.8,64.474 90.8,68.995 cw(c90.875,68.995) 90.822,69.048 92.412,70.638 ccw(c92.2,70.85) 92.474,70.728 cw(c92.543,70.698) 92.49,70.751 92.817,71.078 cw(c92.87,71.025) 92.87,71.1 94.245,71.1 cw(c94.245,71.025) 94.298,71.078 94.342,71.034 cw(c94.289,70.981) 94.364,70.981 94.364,69.65 cw(c94.289,69.65) 94.289,69.575 92.601,69.575 92.188,69.162 ccw(c92.4,68.95) 92.1,68.95 92.1,64.6 ccw(c92.4,64.6) 92.188,64.388 92.528,64.048 cw(c92.475,63.995) 92.55,63.995 92.55,61.05 cw(c92.475,61.05) 92.446,60.981
AGND on TOP "TOP14" (solid, pour order 21): 90.805,54.05 cw(c90.805,54.125) 90.752,54.072 90.422,54.402 cw(c90.475,54.455) 90.4,54.455 90.4,56.7 ccw(c90.1,56.7) 90.391,56.771 cw(c90.464,56.79) 90.389,56.79 90.389,56.8 cw(c90.443,56.852) 90.374,56.822 ccw(c90.1,56.7) 90.312,56.912 89.4,57.824 89.4,57.825 89.024,58.2 88.505,58.2 cw(c88.505,58.275) 88.452,58.222 87.322,59.352 cw(c87.375,59.405) 87.3,59.405 87.3,61.475 cw(c87.375,61.475) 87.375,61.55 87.45,61.55 ccw(c87.45,61.8) 87.469,61.551 cw(c87.475,61.476) 87.475,61.551 88.025,61.551 cw(c88.025,61.476) 88.031,61.551 ccw(c88.05,61.8) 88.05,61.55 88.45,61.55 ccw(c88.45,61.8) 88.7,61.8 88.7,62.2 ccw(c88.45,62.2) 88.45,62.45 87.775,62.45 cw(c87.775,62.525) 87.7,62.525 87.7,64.013 cw(c87.775,64.013) 87.71,64.05 ccw(c87.45,64.2) 87.75,64.2 87.75,64.85 cw(c87.825,64.85) 87.825,64.925 88.05,64.925 ccw(c88.05,65.175) 88.3,65.175 88.3,68.825 cw(c88.375,68.825) 88.375,68.9 88.845,68.9 cw(c88.845,68.825) 88.898,68.878 90.178,67.598 cw(c90.125,67.545) 90.2,67.545 90.2,64.474 cw(c90.125,64.474) 90.165,64.411 ccw(c90.3,64.2) 90.05,64.2 90.05,61.075 cw(c89.975,61.075) 89.975,61 88.65,61 ccw(c88.65,60.75) 88.4,60.75 88.4,59.25 ccw(c88.65,59.25) 88.65,59 91.519,59 cw(c91.519,58.925) 91.572,58.978 91.678,58.872 cw(c91.625,58.819) 91.7,58.819 91.7,54.481 cw(c91.625,54.481) 91.678,54.428 91.322,54.072 cw(c91.269,54.125) 91.269,54.05
GNDX on TOP "TOP15" (solid, pour order 22): 111.075,21 cw(c111.075,21.075) 111,21.075 111,103.925 cw(c111.075,103.925) 111.075,104 148.925,104 cw(c148.925,103.925) 149,103.925 149,21.075 cw(c148.925,21.075) 148.925,21
GND on TOP "TOP16" (solid, pour order 23): 222 vertices, not listed, extent 77.4,21 109,52.25
GND on TOP "TOP17" (solid, pour order 24): 246 vertices, not listed, extent 74.5,42.85 109,104
N16846127 on TOP "TOP18" (solid, pour order 25): 24.575,91 cw(c24.575,91.075) 24.5,91.075 24.5,93.925 cw(c24.575,93.925) 24.575,94 31.675,94 cw(c31.675,93.925) 31.75,93.925 31.75,91.075 cw(c31.675,91.075) 31.675,91
PGND on TOP "TOP19" (solid, pour order 26): 39.325,60 cw(c39.325,60.075) 39.25,60.075 39.25,63.925 cw(c39.325,63.925) 39.325,64 43.675,64 cw(c43.675,63.925) 43.75,63.925 43.75,60.075 cw(c43.675,60.075) 43.675,60
N16845354 on TOP "TOP20" (solid, pour order 27): 24.575,61.5 cw(c24.575,61.575) 24.5,61.575 24.5,64.425 cw(c24.575,64.425) 24.575,64.5 31.675,64.5 cw(c31.675,64.425) 31.75,64.425 31.75,61.575 cw(c31.675,61.575) 31.675,61.5
N16854424 on TOP "TOP21" (solid, pour order 28): 24.575,50.5 cw(c24.575,50.575) 24.5,50.575 24.5,53.425 cw(c24.575,53.425) 24.575,53.5 29.675,53.5 cw(c29.675,53.425) 29.75,53.425 29.75,50.575 cw(c29.675,50.575) 29.675,50.5
N16845627 on TOP "TOP22" (solid, pour order 29): 58.575,41.75 cw(c58.575,41.825) 58.5,41.825 58.5,43.425 cw(c58.575,43.425) 58.575,43.5 62.175,43.5 cw(c62.175,43.425) 62.25,43.425 62.25,41.825 cw(c62.175,41.825) 62.175,41.75
N16846795 on TOP "TOP23" (solid, pour order 30): 58.075,33.5 cw(c58.075,33.575) 58,33.575 58,35.425 cw(c58.075,35.425) 58.075,35.5 59.925,35.5 cw(c59.925,35.425) 60,35.425 60,33.575 cw(c59.925,33.575) 59.925,33.5
PGND on TOP "TOP24" (solid, pour order 31): 39.781,54.25 cw(c39.781,54.325) 39.728,54.272 39.272,54.728 cw(c39.325,54.781) 39.25,54.781 39.25,58.175 cw(c39.325,58.175) 39.325,58.25 43.675,58.25 cw(c43.675,58.175) 43.75,58.175 43.75,54.325 cw(c43.675,54.325) 43.675,54.25
PGND on TOP "TOP25" (solid, pour order 32): 37.575,24 cw(c37.575,24.075) 37.5,24.075 37.5,27.925 cw(c37.575,27.925) 37.575,28 41.925,28 cw(c41.925,27.925) 42,27.925 42,24.075 cw(c41.925,24.075) 41.925,24
N16845280 on TOP "TOP26" (solid, pour order 33): 46.325,24.5 cw(c46.325,24.575) 46.25,24.575 46.25,27.425 cw(c46.325,27.425) 46.325,27.5 51.175,27.5 cw(c51.175,27.425) 51.25,27.425 51.25,24.575 cw(c51.175,24.575) 51.175,24.5
N16845252 on TOP "TOP27" (solid, pour order 34): 53.575,23 cw(c53.575,23.075) 53.5,23.075 53.5,27.425 cw(c53.575,27.425) 53.575,27.5 56.675,27.5 cw(c56.675,27.425) 56.75,27.425 56.75,25.5 57.25,25 61,25 61.478,25.478 cw(c61.531,25.425) 61.531,25.5 63.175,25.5 cw(c63.175,25.425) 63.25,25.425 63.25,24.781 cw(c63.175,24.781) 63.228,24.728 61.522,23.022 cw(c61.469,23.075) 61.469,23
N16847824 on TOP "TOP28" (solid, pour order 35): 47.825,59.5 cw(c47.825,59.575) 47.75,59.575 47.75,63.925 cw(c47.825,63.925) 47.825,64 52.925,64 cw(c52.925,63.925) 53,63.925 53,59.575 cw(c52.925,59.575) 52.925,59.5
N16845404 on TOP "TOP29" (solid, pour order 36): 57.825,27.2 cw(c57.825,27.275) 57.75,27.275 57.75,28.25 53.075,28.25 cw(c53.075,28.325) 53,28.325 53,30.675 cw(c53.075,30.675) 53.075,30.75 57.926,30.75 cw(c57.926,30.675) 57.979,30.728 59.579,29.129 ccw(c61.7,31.25) 60.456,28.52 cw(c60.425,28.452) 60.478,28.505 cw(c60.425,28.452) 60.5,28.452 60.5,27.275 cw(c60.425,27.275) 60.425,27.2
N16845798 on TOP "TOP30" (solid, pour order 37): 58.075,47.5 cw(c58.075,47.575) 58,47.575 58,50.425 cw(c58.075,50.425) 58.075,50.5 63.175,50.5 cw(c63.175,50.425) 63.25,50.425 63.25,48.785 cw(c63.175,48.785) 63.127,48.728 ccw(c62.515,48.001) 61.565,47.996 cw(c61.49,47.996) 61.561,47.973 61.432,47.566 cw(c61.361,47.589) 61.414,47.536 61.399,47.522 cw(c61.346,47.575) 61.346,47.5
N16845404 on TOP "TOP31" (solid, pour order 38): 54.283,51.998 cw(c54.283,52.073) 54.23,52.02 52,54.25 47.825,54.25 cw(c47.825,54.325) 47.75,54.325 47.75,58.175 cw(c47.825,58.175) 47.825,58.25 52.719,58.25 cw(c52.719,58.175) 52.772,58.228 52.773,58.227 56.5,54.5 60.719,54.5 cw(c60.719,54.425) 60.772,54.478 61.25,54 63.175,54 cw(c63.175,53.925) 63.25,53.925 63.25,52.075 cw(c63.175,52.075) 63.175,52 54.391,52 54.286,51.998 54.283,51.998
N16845623 on TOP "TOP32" (solid, pour order 39): 61.531,54.5 cw(c61.531,54.575) 61.478,54.522 61.272,54.728 cw(c61.325,54.781) 61.25,54.781 61.25,56 60.75,56.5 56.781,56.5 cw(c56.781,56.575) 56.728,56.522 55.022,58.228 cw(c55.075,58.281) 55,58.281 55,62.425 cw(c55.075,62.425) 55.075,62.5 58.548,62.5 cw(c58.548,62.425) 58.587,62.489 ccw(c66.25,75.5) 63.19,60.713 cw(c63.175,60.64) 63.199,60.711 cw(c63.175,60.64) 63.25,60.64 63.25,54.575 cw(c63.175,54.575) 63.175,54.5
N16846795 on TOP "TOP33" (solid, pour order 40): 61.031,29.75 cw(c61.031,29.825) 60.978,29.772 60.522,30.228 cw(c60.575,30.281) 60.5,30.281 60.5,32.675 cw(c60.575,32.675) 60.575,32.75 63.175,32.75 cw(c63.175,32.675) 63.25,32.675 63.25,29.825 cw(c63.175,29.825) 63.175,29.75
N16847047 on TOP "TOP34" (solid, pour order 41): 24.575,39.5 cw(c24.575,39.575) 24.5,39.575 24.5,42.425 cw(c24.575,42.425) 24.575,42.5 31.925,42.5 cw(c31.925,42.425) 32,42.425 32,39.575 cw(c31.925,39.575) 31.925,39.5
GND on TOP "TOP35" (solid, pour order 42): 76.817,49.7 cw(c76.817,49.775) 76.764,49.722 76.672,49.814 cw(c76.725,49.867) 76.65,49.867 76.65,52.12 ccw(c76.2,52.12) 76.648,52.167 cw(c76.722,52.175) 76.722,52.25 78.957,52.25 cw(c78.957,52.175) 79.01,52.228 79.128,52.111 cw(c79.075,52.058) 79.15,52.058 79.15,51.025 cw(c79.075,51.025) 79.075,50.95 78.4,50.95 ccw(c78.4,50.7) 78.157,50.758 cw(c78.084,50.775) 78.084,50.7 77.3,50.7 ccw(c77.3,50.45) 77.05,50.45 77.05,49.775 cw(c76.975,49.775) 76.975,49.7
GNDX on BOTTOM "BOTTOM36" (solid, pour order 2): 111.075,21 cw(c111.075,21.075) 111,21.075 111,103.925 cw(c111.075,103.925) 111.075,104 148.925,104 cw(c148.925,103.925) 149,103.925 149,21.075 cw(c148.925,21.075) 148.925,21
AGND on BOTTOM "BOTTOM37" (solid, pour order 3): 90.175,48.7 cw(c90.175,48.775) 90.1,48.775 90.1,52.425 cw(c90.175,52.425) 90.175,52.5 93.5,52.5 ccw(c93.5,53) 93.323,53.468 93.321,53.467 93.32,53.467 93.028,53.355 cw(c93.002,53.425) 93.002,53.35 88.426,53.35 cw(c88.426,53.425) 88.373,53.372 87.1,54.645 cw(c87.153,54.698) 87.086,54.665 87.085,54.667 86.957,54.954 86.956,54.955 86.955,54.957 ccw(c86.5,54.75) 86.02,54.891 85.943,54.63 cw(c85.871,54.651) 85.924,54.598 85.148,53.822 cw(c85.095,53.875) 85.095,53.8 81.75,53.8 ccw(c81.75,53.5) 81.667,53.788 cw(c81.646,53.86) 81.593,53.807 80.872,54.528 cw(c80.925,54.581) 80.85,54.581 80.85,62.419 cw(c80.925,62.419) 80.872,62.472 83.4,65 83.4,71.975 cw(c83.475,71.975) 83.475,72.05 93.533,72.05 cw(c93.533,71.975) 93.586,72.028 94.342,71.272 cw(c94.289,71.219) 94.364,71.219 94.364,69.281 cw(c94.289,69.281) 94.342,69.228 93.682,68.568 ccw(c94,68.25) 93.55,68.25 93.55,64.735 cw(c93.475,64.735) 93.543,64.704 ccw(c94,64.5) 94.429,64.242 cw(c94.493,64.204) 94.44,64.257 95.711,65.528 cw(c95.764,65.475) 95.763,65.55 ccw(c95.75,66.25) 96.24,65.75 ccw(c95.75,66.25) 96.45,66.25 96.45,66.429 cw(c96.525,66.429) 96.472,66.482 96.518,66.528 cw(c96.571,66.475) 96.571,66.55 97.179,66.55 cw(c97.179,66.475) 97.232,66.528 97.528,66.232 cw(c97.475,66.179) 97.55,66.179 97.55,64.571 cw(c97.475,64.571) 97.528,64.518 96.757,63.747 96.753,63.743 94.482,61.472 cw(c94.429,61.525) 94.429,61.45 85.5,61.45 ccw(c85.5,60.75) 85.005,61.245 82.507,58.747 ccw(c83,58.25) 82.507,57.753 83.76,56.5 83.855,56.405 ccw(c84.35,56.9) 84.35,56.2 92.779,56.2 cw(c92.779,56.125) 92.832,56.178 95.028,53.982 cw(c94.975,53.929) 95.05,53.929 95.05,51.571 cw(c94.975,51.571) 95.028,51.518 92.232,48.722 cw(c92.179,48.775) 92.179,48.7
N16845404 on BOTTOM "BOTTOM38" (solid, pour order 4): 53.281,28.5 cw(c53.281,28.575) 53.228,28.522 53.022,28.728 cw(c53.075,28.781) 53,28.781 53,31.469 cw(c53.075,31.469) 53.022,31.522 53.023,31.523 53.258,31.758 cw(c53.311,31.705) 53.311,31.78 54,31.78 ccw(c54,33.98) 56.2,33.98 56.2,48.47 ccw(c54,48.48) 53.831,50.674 cw(c53.825,50.748) 53.825,50.673 cw(c53.825,50.748) 53.75,50.748 53.75,53.925 cw(c53.825,53.925) 53.825,54 58.925,54 cw(c58.925,53.925) 59,53.925 59,31.031 cw(c58.925,31.031) 58.978,30.978 58.977,30.977 56.522,28.522 cw(c56.469,28.575) 56.469,28.5
PGND on BOTTOM "BOTTOM39" (solid, pour order 5): 37.781,24 cw(c37.781,24.075) 37.728,24.022 33.272,28.478 cw(c33.325,28.531) 33.25,28.531 33.25,69.5 27.022,75.728 cw(c27.075,75.781) 27,75.781 27,81.675 cw(c27.075,81.675) 27.075,81.75 29.925,81.75 cw(c29.925,81.675) 30,81.675 30,77 36.228,70.772 cw(c36.175,70.719) 36.25,70.719 36.25,64.75 36.75,64.25 40.719,64.25 cw(c40.719,64.175) 40.772,64.228 41.228,63.772 cw(c41.175,63.719) 41.25,63.719 41.25,54.531 cw(c41.175,54.531) 41.228,54.478 41.022,54.272 cw(c40.969,54.325) 40.969,54.25 37,54.25 36.25,53.5 36.25,30.75 38.75,28.25 39.675,28.25 cw(c39.675,28.175) 39.75,28.175 39.75,24.075 cw(c39.675,24.075) 39.675,24
GND on BOTTOM "BOTTOM40" (solid, pour order 6): 187 vertices, not listed, extent 74.25,21 109,104
GND on BOTTOM "BOTTOM41" (solid, pour order 7): 76.01,43.6 cw(c76.01,43.675) 75.935,43.675 75.935,51.408 cw(c76.01,51.408) 75.938,51.429 76.121,52.044 cw(c76.193,52.022) 76.14,52.075 77.168,53.104 ccw(c76.85,53.422) 77.3,53.422 77.3,53.649 cw(c77.375,53.649) 77.301,53.658 77.346,54.04 ccw(c76.85,54.1) 76.85,54.6 76.01,54.6 cw(c76.01,54.675) 75.935,54.675 75.935,60.175 cw(c76.01,60.175) 76.01,60.25 79.425,60.25 cw(c79.425,60.175) 79.5,60.175 79.5,51.705 cw(c79.425,51.705) 79.478,51.652 79.188,51.362 ccw(c79.4,51.15) 79.1,51.15 79.1,43.675 cw(c79.025,43.675) 79.025,43.6

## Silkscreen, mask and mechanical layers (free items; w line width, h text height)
Top Overlay:
  lines w0.15: 76.6,58.25 82.725,58.25 ; 77.5,48.75 77.5,48 77.75,47.75 79,47.75 79.25,47.5 ; 83.275,58.25 86.385,58.25 ; 84.5,57.25 84.5,58.25 ; 86.615,58.25 87,58.25 87,57.5 ; 92.5,61.25 92.75,61.5 95,61.5 95.25,61.75 95.5,62 95.25,62 ; 97.5,59.5 98,59.5 98.25,59.25 98.25,58.5 98.5,58.75 ; 101.25,26.5 101.75,26 ; 101.75,27.5 101.75,26 ; 102.25,26.5 101.75,26 ; 74.15,58.25 76.65,58.25 76.65,61.25 74.15,61.25 74.15,58.25
  text "DC INPUT" at 27.82,98.85 h1.17
  text "120-340V" at 27.82,96.85 h1.17
  text "+" at 31.825,95.1 h1.35
  text "DVSS" at 103.05,93.6 h1.35
  text "EXT.DAC" at 122.525,91.1 h1.35
  text "DC5V" at 102.15,90.55 h1.35 r90
  text "DC15V" at 76.1,88.525 h1.35 r90
  text "DVDD" at 93.75,86.65 h1.35
  text "RESET" at 83.875,85.6 h1.35
  text "SWD" at 144.15,84.975 h1.35 r90
  text "FUSE 440V-10A" at 53.05,84.595 h1.17 r90
  text "EXT.CONTROL" at 99.825,70.825 h1.35 r90
  text "-" at 31.825,69.1 h1.35
  text "GND" at 33.745,68.85 h1.17
  text "U" at 32.825,65.6 h1.35
  text "AD_V" at 94.4,62.15 h1.35
  text "AD_W" at 76.9,59.9 h1.35
  text "AD_U" at 95.2,56.6 h1.35
  text "BOOT" at 140.3,56.6 h1.35
  text "V" at 37.325,52.35 h1.35
  text "EMG" at 80.975,49.85 h1.35
  text "DEBUG" at 100.35,47.825 h1.35 r90
  text "AVSS" at 95.3,45.55 h1.35
  text "AVDD" at 80.55,43.85 h1.35
  text "RELAY" at 139.4,38.625 h1.35 r90
  text "METIS-4164K" at 114.15,29.575 h1.35 r90
  text "W" at 32.825,28.35 h1.35
  text "RELAY" at 102.425,27.5 h1.35
  text "UL" at 82.45,25.9 h1.35
  text "WL" at 96.45,25.9 h1.35
  text "UH" at 78.9,25.85 h1.35
  text "VH" at 85.9,25.85 h1.35
  text "VL" at 89.4,25.85 h1.35
  text "WH" at 92.65,25.85 h1.35
  text "METIS-" at 28.95,25.1 h1.35
  text "4164K" at 28.625,22.1 h1.35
